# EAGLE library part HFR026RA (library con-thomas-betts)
THOMAS&BETTS
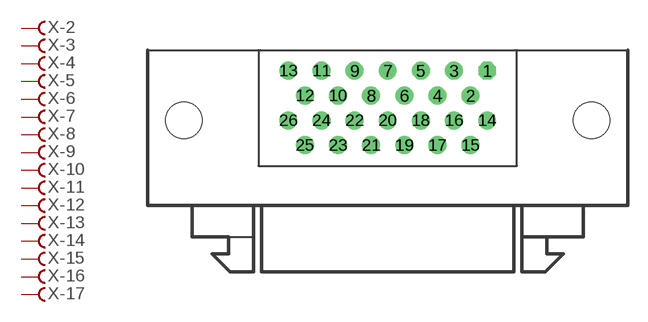
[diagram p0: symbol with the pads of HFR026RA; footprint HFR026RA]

Designator prefix X; gates -2=F -3=F -4=F -5=F -6=F -7=F -8=F -9=F -10=F -11=F -12=F -13=F -14=F -15=F -16=F -17=F -18=F -19=F -20=F -21=F -22=F -23=F -24=F -25=F -26=F -1=FV

## HFR026RA  [HFR026RA]
1  -1:F  pas
2  -2:F  pas
3  -3:F  pas
4  -4:F  pas
5  -5:F  pas
6  -6:F  pas
7  -7:F  pas
8  -8:F  pas
9  -9:F  pas
10  -10:F  pas
11  -11:F  pas
12  -12:F  pas
13  -13:F  pas
14  -14:F  pas
15  -15:F  pas
16  -16:F  pas
17  -17:F  pas
18  -18:F  pas
19  -19:F  pas
20  -20:F  pas
21  -21:F  pas
22  -22:F  pas
23  -23:F  pas
24  -24:F  pas
25  -25:F  pas
26  -26:F  pas

## Footprint HFR026RA (pad centres in mm)
THOMAS&BETTS
drill 0.864 octagon: 1 7.62,8.89
drill 0.864 round: 2 6.35,6.985; 3 5.08,8.89; 4 3.81,6.985; 5 2.54,8.89; 6 1.27,6.985; 7 0,8.89; 8 -1.27,6.985; 9 -2.54,8.89; 10 -3.81,6.985; 11 -5.08,8.89; 12 -6.35,6.985; 13 -7.62,8.89; 14 7.62,5.08; 15 6.35,3.175; 16 5.08,5.08; 17 3.81,3.175; 18 2.54,5.08; 19 1.27,3.175; 20 0,5.08; 21 -1.27,3.175; 22 -2.54,5.08; 23 -3.81,3.175; 24 -5.08,5.08; 25 -6.35,3.175; 26 -7.62,5.08
hole 2.769 at 15.621,5.08
hole 2.769 at -15.621,5.08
